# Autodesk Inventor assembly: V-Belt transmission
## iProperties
Created: 2011-05
Part Number: V-Belt transmission
Document SubType Name: Assembly
Designer: 904Chiaki
ClientObjectVersion: 1
Author: 904Chiaki
